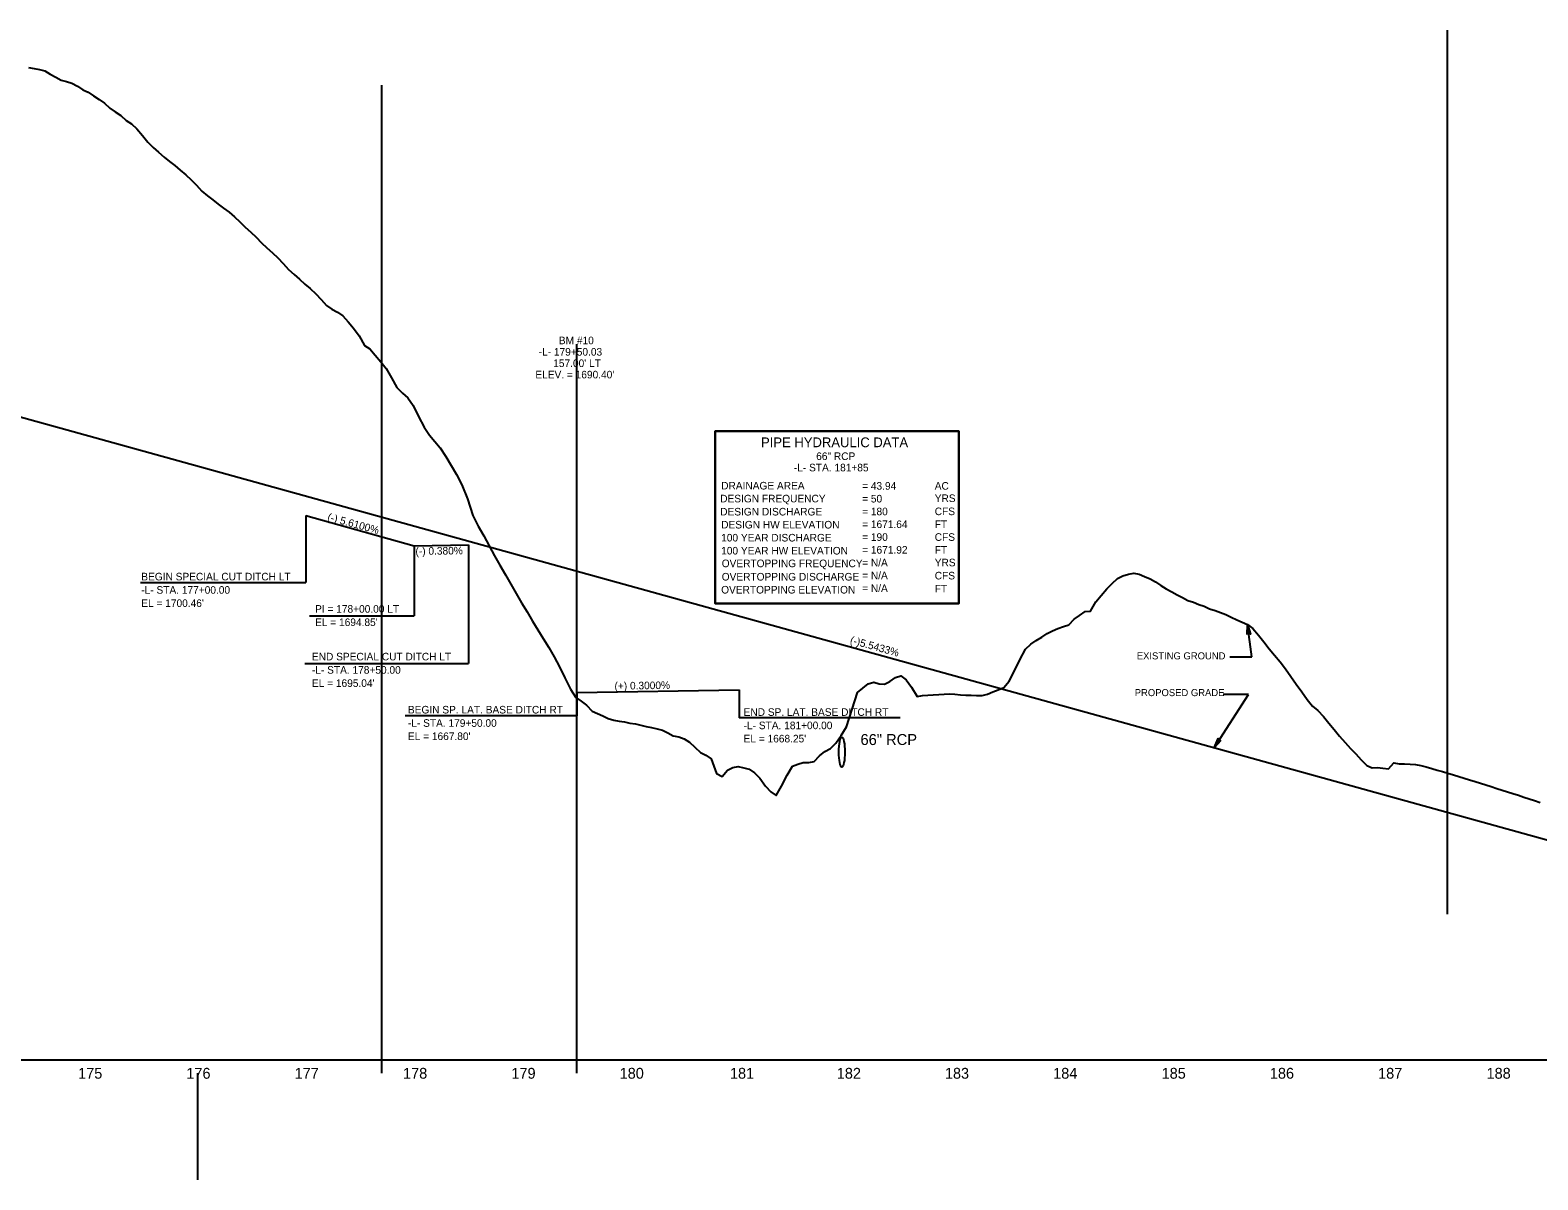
# Model space of a CAD drawing. Extents: x 498575 to 532350, y 405181 to 484585.
# Drawn here: x 522265 to 523656, y 483123 to 484184 of the extents above; entities that cross this region are included whole.
import ezdxf

# ---------------------------------------------------------------- set-up
doc = ezdxf.new("R2010")
doc.units = 0
for name, color, linetype in [('Exist Profile Cell', 7, 'Continuous'), ('Exist Vertical Profile Ground Line', 7, 'Continuous'), ('Exist Vertical Profile Horizontal Axis Label Major', 7, 'Continuous'), ('Prop Drainage Structure Pipe Welded Steel 54in Label', 7, 'Continuous'), ('Prop Grid Mask', 7, 'Continuous'), ('Prop PFL Text', 7, 'Continuous'), ('Prop Vertical Profile Ditch Grade Left', 7, 'Continuous'), ('Prop Vertical Profile Ditch Grade Left Label', 7, 'Continuous'), ('Prop Vertical Profile Ditch Grade Right', 7, 'Continuous'), ('Prop Vertical Profile Ditch Grade Right Label', 7, 'Continuous'), ('Prop Vertical Profile Grade', 7, 'Continuous'), ('Prop Vertical Profile Grade Label', 7, 'Continuous'), ('Scratch_Level_0', 7, 'Continuous'), ('Scratch_Level_4', 7, 'Continuous'), ('Scratch_Level_5', 7, 'Continuous'), ('Sheet Data Text CELL', 7, 'Continuous'), ('Sheet Profile Grid Minor CELL', 7, 'Continuous')]:
    doc.layers.add(name, color=color, linetype=linetype)

msp = doc.modelspace()

# ---------------------------------------------------------------- linework, layer by layer
at = {"layer": 'Exist Profile Cell'}
msp.add_line((505856.7, 483233.7), (526056.7, 483233.7), dxfattribs=at)
at = {"layer": 'Exist Vertical Profile Ground Line'}
for points in [[(522263.2, 484149.3), (522268.2, 484148.4), (522273.2, 484147.4), (522278.2, 484146.1), (522283.2, 484143.2), (522288.2, 484140.2), (522293.2, 484137.6), (522298.2, 484136.2), (522303.2, 484134.9), (522308.2, 484132.1), (522313.2, 484128.8)], [(522313.2, 484128.8), (522318.2, 484126.4), (522323.2, 484123.1), (522328.2, 484119.8), (522333.2, 484116.5), (522338.2, 484111.7), (522343.2, 484108.4), (522348.2, 484105.1), (522353.2, 484100.4), (522358.2, 484097.2), (522363.2, 484092.6), (522368.2, 484086.5), (522373.2, 484080.5), (522378.2, 484075.5), (522383.2, 484071), (522388.2, 484066.4), (522393.2, 484062.6), (522398.2, 484058.8), (522403.2, 484054.6), (522408.2, 484050.1), (522413.2, 484045.7), (522418.2, 484040.7), (522423.2, 484035.3), (522428.2, 484030.8), (522433.2, 484027.1), (522438.2, 484023.3), (522443.2, 484019.5), (522448.2, 484015.8), (522453.2, 484011.5), (522458.2, 484006.9), (522463.2, 484001.9), (522468.2, 483997.2), (522473.2, 483992.8), (522478.2, 483987.6), (522483.2, 483982.9), (522488.2, 483978.2), (522493.2, 483973.6), (522498.2, 483968.4), (522503.2, 483962.8), (522508.2, 483958.2), (522513.2, 483953.9), (522518.2, 483949.4), (522523.2, 483945.2), (522528.2, 483940.5), (522533.2, 483935.2), (522538.2, 483929.8), (522543.2, 483926.3), (522548.2, 483923.5), (522553.2, 483920.2), (522558.2, 483914.5), (522563.2, 483908.8), (522568.2, 483901.7), (522573.2, 483892.7), (522578.2, 483889.8), (522583.2, 483883.9), (522588.2, 483877.8), (522593.2, 483871.4), (522598.2, 483863), (522603.2, 483854), (522608.2, 483848.8), (522613.2, 483844.5), (522618.2, 483837.3), (522623.2, 483827.3), (522628.2, 483817.3), (522633.2, 483810.1), (522638.2, 483804.2), (522643.2, 483798.3), (522648.2, 483790.4), (522653.2, 483782), (522658.2, 483773.6), (522663.2, 483764.2), (522668.2, 483751.2), (522673.2, 483735.8), (522678.2, 483726.1), (522683.2, 483717), (522688.2, 483707.8), (522693.2, 483698.6), (522698.2, 483689.9), (522703.2, 483681.2), (522708.2, 483672.6), (522713.2, 483663.9), (522718.2, 483655.4), (522723.2, 483647), (522728.2, 483638.5), (522733.2, 483630.4), (522738.2, 483622.4), (522743.2, 483614.2), (522748.2, 483605.4), (522753.2, 483596.2), (522758.2, 483586), (522763.2, 483575.6), (522768.2, 483567.8), (522773.2, 483564.5), (522778.2, 483560.9), (522783.2, 483555.3), (522788.2, 483553.2), (522793.2, 483551), (522798.2, 483548.7), (522803.2, 483547), (522808.2, 483546.2), (522813.2, 483545.4)], [(522813.2, 483545.4), (522818.2, 483544.4), (522823.2, 483543.5), (522828.2, 483542.5), (522833.2, 483541.3), (522838.2, 483540.4), (522843.2, 483539.1), (522848.2, 483537.9), (522853.2, 483535.4), (522858.2, 483532.7), (522863.2, 483531.7), (522868.2, 483529.9), (522873.2, 483526.8), (522878.2, 483522.1), (522883.2, 483517.2), (522888.2, 483514.6), (522893.2, 483511.5), (522898.2, 483497.8), (522903.2, 483495.1), (522908.2, 483500.8), (522913.2, 483503.3), (522918.2, 483504.2), (522923.2, 483503), (522928.2, 483501.7), (522933.2, 483498.3), (522938.2, 483493.6), (522943.2, 483486.2), (522948.2, 483481), (522953.2, 483477.6), (522958.2, 483486.2), (522963.2, 483496.2), (522968.2, 483504.6), (522973.2, 483506.5), (522978.2, 483508), (522983.2, 483508.1), (522988.2, 483508.9), (522993.2, 483514.2), (522998.2, 483518), (523003.2, 483520.9), (523008.2, 483525.8), (523013.2, 483532.9), (523018.2, 483540.8), (523023.2, 483557.3), (523028.2, 483572.7), (523033.2, 483576.5), (523038.2, 483580.7), (523043.2, 483582.2), (523048.2, 483580.7), (523053.2, 483580.3), (523058.2, 483582.7), (523063.2, 483586.3), (523068.2, 483587.9), (523073.2, 483584.2), (523078.2, 483577.4), (523083.2, 483568.8), (523088.2, 483569.8), (523093.2, 483570.2), (523098.2, 483570.3), (523103.2, 483570.7), (523108.2, 483571.1), (523113.2, 483571.3), (523118.2, 483570.9), (523123.2, 483570.5), (523128.2, 483570.2), (523133.2, 483570), (523138.2, 483569.7), (523143.2, 483569.7), (523148.2, 483571.1), (523153.2, 483573.1), (523158.2, 483575.1), (523163.2, 483577.1), (523168.2, 483583), (523173.2, 483592.6), (523178.2, 483602.6), (523183.2, 483612.5), (523188.2, 483617.1), (523193.2, 483620.4), (523198.2, 483623.7), (523203.2, 483627), (523208.2, 483629.4), (523213.2, 483631.5), (523218.2, 483633.5), (523223.2, 483635.1), (523228.2, 483640.1), (523233.2, 483643.7), (523238.2, 483647.2), (523243.2, 483647.6), (523248.2, 483656.3), (523253.2, 483662), (523258.2, 483668.1), (523263.2, 483673.2), (523268.2, 483677.6), (523273.2, 483680.1), (523278.2, 483681.9), (523283.2, 483682.8), (523288.2, 483681.8), (523293.2, 483679.7), (523298.2, 483677.4), (523303.2, 483674.7), (523308.2, 483671.3), (523313.2, 483668.2)], [(523313.2, 483668.2), (523318.2, 483665.4), (523323.2, 483662.7), (523328.2, 483660.1), (523333.2, 483657.6), (523338.2, 483655.8), (523343.2, 483653.9), (523348.2, 483652.1), (523353.2, 483649.9), (523358.2, 483648.1), (523363.2, 483646.3), (523368.2, 483644.5), (523373.2, 483642.2), (523378.2, 483639.5), (523383.2, 483637.4), (523388.2, 483635.2), (523393.2, 483631.6), (523398.2, 483625.6), (523403.2, 483619.2), (523408.2, 483613), (523413.2, 483606.9), (523418.2, 483600.9), (523423.2, 483594.4), (523428.2, 483587.3), (523433.2, 483580.2), (523438.2, 483573.1), (523443.2, 483566.1), (523448.2, 483560.1), (523453.2, 483555.9), (523458.2, 483550.4), (523463.2, 483544.3), (523468.2, 483538.3), (523473.2, 483532.4), (523478.2, 483526.5), (523483.2, 483521), (523488.2, 483515.9), (523493.2, 483510.5), (523498.2, 483505.1), (523503.2, 483503.1), (523508.2, 483503.3), (523513.2, 483502.6), (523518.2, 483502.2), (523523.2, 483507.8), (523528.2, 483506.8), (523533.2, 483506.7), (523538.2, 483506.3), (523543.2, 483506), (523548.2, 483505.2), (523553.2, 483503.9), (523558.2, 483502.5), (523563.2, 483501), (523568.2, 483499.6), (523573.2, 483498.1), (523578.2, 483496.5), (523583.2, 483495), (523588.2, 483493.5), (523593.2, 483491.9), (523598.2, 483490.4), (523603.2, 483488.9), (523608.2, 483487.3), (523613.2, 483485.7), (523618.2, 483484.1), (523623.2, 483482.5), (523628.2, 483480.9), (523633.2, 483479.3), (523638.2, 483477.7), (523643.2, 483476.1), (523648.2, 483474.5), (523653.2, 483472.8), (523658.2, 483471.2)]]:
    msp.add_lwpolyline(points, dxfattribs=at)
at = {"layer": 'Prop Drainage Structure Pipe Welded Steel 54in Label'}
msp.add_ellipse((523013.8, 483517.6), major_axis=(0, 13.8), ratio=0.2, dxfattribs=at)
at = {"layer": 'Prop Grid Mask'}
msp.add_lwpolyline([(522896.9, 483813.8), (523121.9, 483813.8), (523121.9, 483654.8), (522896.9, 483654.8)], close=True, dxfattribs=at)
at = {"layer": 'Prop PFL Text'}
for p, q in [((523392.3, 483605.6), (523388.1, 483635.2)), ((523371.9, 483605.6), (523392.3, 483605.6)), ((523357.5, 483521.5), (523389, 483570.7)), ((523389, 483570.7), (523365.6, 483570.7))]:
    msp.add_line(p, q, dxfattribs=at)
for points in [[(523387.8, 483626.1), (523388.1, 483635.2), (523391, 483626.5), (523389.2, 483627.4)], [(523363.6, 483528.3), (523357.5, 483521.5), (523361, 483530), (523361.7, 483528.2)]]:
    msp.add_lwpolyline(points, close=True, dxfattribs=at)
at = {"layer": 'Prop Vertical Profile Ditch Grade Left'}
msp.add_lwpolyline([(522519.1, 483736), (522619.1, 483708), (522669.1, 483708.9), (522669.1, 483708.9)], dxfattribs=at)
at = {"layer": 'Prop Vertical Profile Ditch Grade Left Label'}
for p, q in [((522519.1, 483736), (522519.1, 483674)), ((522619.1, 483708), (522619.1, 483643.4)), ((522669.1, 483708.9), (522669.1, 483599.4)), ((522366.4, 483674), (522519.1, 483674)), ((522522.3, 483643.4), (522619.1, 483643.4)), ((522518, 483599.4), (522669.1, 483599.4))]:
    msp.add_line(p, q, dxfattribs=at)
at = {"layer": 'Prop Vertical Profile Ditch Grade Right'}
msp.add_lwpolyline([(522769.1, 483572.7), (522919.1, 483575), (522919.1, 483575)], dxfattribs=at)
at = {"layer": 'Prop Vertical Profile Ditch Grade Right Label'}
for p, q in [((522769.1, 483572.7), (522769.1, 483550.9)), ((522919.1, 483575), (522919.1, 483549.1)), ((522769.1, 483550.9), (522610.8, 483550.9)), ((523067.6, 483549.1), (522919.1, 483549.1))]:
    msp.add_line(p, q, dxfattribs=at)
at = {"layer": 'Prop Vertical Profile Grade'}
msp.add_line((522224.1, 483835.6), (523854.1, 483383.9), dxfattribs=at)
at = {"layer": 'Scratch_Level_0'}
msp.add_line((522769.1, 483221.2), (522769.1, 483893.9), dxfattribs=at)
at = {"layer": 'Scratch_Level_4'}
msp.add_line((523572.3, 484183.7), (523572.3, 483368.1), dxfattribs=at)
at = {"layer": 'Scratch_Level_5'}
msp.add_line((522589.1, 483221.2), (522589.1, 484133.1), dxfattribs=at)
at = {"layer": 'Sheet Data Text CELL'}
msp.add_lwpolyline([(522896.9, 483654.8), (523121.9, 483654.8), (523121.9, 483813.8), (522896.9, 483813.8)], close=True, dxfattribs=at)
at = {"layer": 'Sheet Profile Grid Minor CELL'}
msp.add_line((522419.1, 483221.2), (522419.1, 483122.9), dxfattribs=at)

# ---------------------------------------------------------------- texts
at = {"layer": 'Exist Vertical Profile Horizontal Axis Label Major'}
for s, p in [('175', (522308.9, 483216.2)), ('175', (522308.9, 483216.2)), ('176', (522408.8, 483216.2)), ('176', (522408.8, 483216.2)), ('177', (522508.7, 483216.2)), ('177', (522508.7, 483216.2)), ('178', (522608.8, 483216.2)), ('178', (522608.8, 483216.2)), ('179', (522708.8, 483216.2)), ('179', (522708.8, 483216.2)), ('180', (522808.7, 483216.2)), ('180', (522808.7, 483216.2)), ('181', (522910.5, 483216.2)), ('181', (522910.5, 483216.2)), ('182', (523009.1, 483216.2)), ('182', (523009.1, 483216.2)), ('183', (523108.9, 483216.2)), ('183', (523108.9, 483216.2)), ('184', (523208.8, 483216.2)), ('184', (523208.8, 483216.2)), ('185', (523308.9, 483216.2)), ('185', (523308.9, 483216.2)), ('186', (523408.8, 483216.2)), ('186', (523408.8, 483216.2)), ('187', (523508.7, 483216.2)), ('187', (523508.7, 483216.2)), ('188', (523608.8, 483216.2)), ('188', (523608.8, 483216.2))]:
    msp.add_text(s, height=10, dxfattribs=at).set_placement(p)
at = {"layer": 'Prop Drainage Structure Pipe Welded Steel 54in Label'}
msp.add_text('66" RCP', height=10.12, dxfattribs=at).set_placement((523031, 483524.1))
at = {"layer": 'Prop PFL Text'}
for s, height, p in [('BM #10', 7, (522752.6, 483893.9)), ('-L- 179+50.03', 7, (522734, 483883.4)), ("157.00' LT", 7, (522747.4, 483872.9)), ("ELEV. = 1690.40'", 7, (522730.9, 483862.4)), ('EXISTING GROUND', 6.516, (523286, 483603.1)), ('PROPOSED GRADE', 6.516, (523284.1, 483569.2))]:
    msp.add_text(s, height=height, dxfattribs=at).set_placement(p)
at = {"layer": 'Prop Vertical Profile Ditch Grade Left Label'}
for s, rotation, p in [('(-) 5.6100%', 344.6607, (522538.4, 483731.5)), ('(-) 0.380%', 0.7304, (522620.3, 483699.5)), ('BEGIN SPECIAL CUT DITCH LT', 360, (522367.2, 483676)), ('-L- STA. 177+00.00', 360, (522367.2, 483663.7)), ("EL = 1700.46'", 360, (522367.2, 483651.5)), ('PI = 178+00.00 LT', 360, (522527.6, 483646.2)), ("EL = 1694.85'", 360, (522527.6, 483633.9)), ('END SPECIAL CUT DITCH LT', 360, (522524.7, 483602.2)), ('-L- STA. 178+50.00', 360, (522524.7, 483589.9)), ("EL = 1695.04'", 360, (522524.7, 483577.7))]:
    msp.add_text(s, height=7, rotation=rotation, dxfattribs=at).set_placement(p)
at = {"layer": 'Prop Vertical Profile Ditch Grade Right Label'}
for s, rotation, p in [('(+) 0.3000%', 0.8982, (522804, 483575.1)), ('BEGIN SP. LAT. BASE DITCH RT', 360, (522613.3, 483553.2)), ('END SP. LAT. BASE DITCH RT', 360, (522923.1, 483551)), ('-L- STA. 179+50.00', 360, (522613.3, 483540.9)), ("EL = 1667.80'", 360, (522613.3, 483528.7)), ('-L- STA. 181+00.00', 360, (522923.1, 483538.7)), ("EL = 1668.25'", 360, (522923.1, 483526.5))]:
    msp.add_text(s, height=7, rotation=rotation, dxfattribs=at).set_placement(p)
at = {"layer": 'Prop Vertical Profile Grade Label'}
msp.add_text('(-)5.5433%', height=7, rotation=344.5085, dxfattribs=at).set_placement((523020.8, 483617.9))
at = {"layer": 'Sheet Data Text CELL'}
for s, height, p in [('PIPE HYDRAULIC DATA', 9, (522939.2, 483798.9)), ('DRAINAGE AREA', 7, (522902.4, 483759.9)), ('AC', 7, (523099.5, 483759.7)), ('DESIGN FREQUENCY', 7, (522901.5, 483748)), ('= 50', 7, (523032.5, 483747.9)), ('YRS', 7, (523099.5, 483748.3)), ('DESIGN DISCHARGE', 7, (522901.5, 483735.9)), ('DESIGN HW ELEVATION', 7, (522902.4, 483723.9)), ('CFS', 7, (523099.5, 483736.2)), ('FT', 7, (523099.5, 483724.3)), ('100 YEAR DISCHARGE', 7, (522902.4, 483711.9)), ('CFS', 7, (523099.5, 483712.5)), ('100 YEAR HW ELEVATION', 7, (522902.4, 483699.9)), ('FT', 7, (523099.5, 483700.7)), ('OVERTOPPING FREQUENCY', 7, (522902.9, 483688.2)), ('YRS', 7, (523099.5, 483689)), ('OVERTOPPING DISCHARGE', 7, (522902.9, 483675.9)), ('CFS', 7, (523099.5, 483676.9)), ('OVERTOPPING ELEVATION', 7, (522902.4, 483663.9)), ('FT', 7, (523099.5, 483664.9))]:
    msp.add_text(s, height=height, rotation=360, dxfattribs=at).set_placement(p)
for s, p in [('66" RCP', (522990.1, 483787.1)), ('-L- STA. 181+85', (522969.5, 483776.6)), ('= 43.94', (523032.5, 483759.7)), ('= 180', (523032.5, 483736.1)), ('= 1671.64', (523032.5, 483724.3)), ('= 190', (523032.5, 483712.5)), ('= 1671.92', (523032.5, 483700.7)), ('= N/A', (523032.5, 483688.9)), ('= N/A', (523032.5, 483677.1)), ('= N/A', (523032.5, 483665.3))]:
    msp.add_text(s, height=7, dxfattribs=at).set_placement(p)

doc.saveas('drawing.dxf')
